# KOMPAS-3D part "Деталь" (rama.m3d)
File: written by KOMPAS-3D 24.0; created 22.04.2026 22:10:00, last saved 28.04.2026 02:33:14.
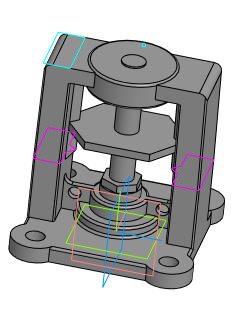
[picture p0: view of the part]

Document properties: Автор: mrdid; Полное имя файла: C:\Работа\ГОТОВЫЕ ИСХОДНИКИ\VSO2130M-F-S Клапан запорный сильфонный DN.ru Ду15-100 Ру40\исходные материалы\DN50\rama.m3d

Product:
- Part/product: Деталь
    Масса: 2.809972

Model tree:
1. Эскиз:2  (with: Ребро.Элемент выдавливания:14)
2. Элемент выдавливания:1
     Расстояние 1 = 10
3. Эскиз:3  (with: Грань.Элемент выдавливания:1, Ребро.Элемент выдавливания:1)
4. Элемент выдавливания:2
     Расстояние 2 = 10
5. Массив по сетке:1  (with: Элемент выдавливания:2, Эскиз:3)  (4 pattern instances)
     Угол раствора = 90
6. Эскиз:4  (with: Грань.Элемент выдавливания:1)
7. Элемент выдавливания:3
     Расстояние 1 = 7
8. Эскиз:5  (with: Грань.Элемент выдавливания:3, Ребро.Элемент выдавливания:3)
9. Элемент выдавливания:4
     Расстояние 1 = 10
10. Эскиз:6  (with: Грань.Элемент выдавливания:1, Ребро.Элемент выдавливания:1)
11. Элемент выдавливания:5
     Расстояние 1 = 40
12. Эскиз:23  (with: Грань.Элемент выдавливания:4, Ребро.Элемент выдавливания:4)
13. Элемент выдавливания:21
     Расстояние 1 = 11
14. Эскиз:7  (with: Грань.Элемент выдавливания:21, Ребро.Элемент выдавливания:3)
15. Элемент выдавливания:6
     Расстояние 2 = 5
16. Эскиз:8  (with: Грань.Элемент выдавливания:5, Ребро.Элемент выдавливания:5)
17. Смещенная плоскость:1  (with: Грань.Элемент выдавливания:5)
18. Эскиз:9
19. Элемент по сечениям:1
20. Элемент по сечениям:2
21. Эскиз:10
22. Элемент выдавливания:8
     Расстояние 2 = 10
23. Эскиз:11  (with: Грань.Элемент выдавливания:8, Ребро.Элемент выдавливания:3)
24. Элемент выдавливания:9  (with: Грань.Элемент выдавливания:8)
     Расстояние 1 = 1; Расстояние 2 = 16; Смещение 2 = 6
25. Эскиз:12  (with: Грань.Элемент выдавливания:9, Ребро.Элемент выдавливания:9)
26. Элемент выдавливания:10
     Расстояние 1 = 5
27. Эскиз:13  (with: Грань.Элемент выдавливания:21, Ребро.Элемент выдавливания:3)
28. Элемент выдавливания:11  (with: Грань.Элемент выдавливания:10)
     Расстояние 1 = 56.64
29. Смещенная плоскость:2  (with: Грань.Элемент выдавливания:21)
30. Эскиз:14  (with: Ребро.Элемент по сечениям:2, Ребро.Элемент по сечениям:1)
31. Элемент выдавливания:12
     Расстояние 1 = 5
32. Эскиз:15  (with: Грань.Элемент выдавливания:12, Ребро.Элемент выдавливания:3)
33. Элемент выдавливания:13
     Расстояние 1 = 5
34. Эскиз:16  (with: Ребро.Элемент выдавливания:5, Ребро.Элемент выдавливания:1, Ребро.Элемент выдавливания:4)
35. Элемент выдавливания:14
     Расстояние 1 = 4
36. Элемент выдавливания:15
     Расстояние 1 = 2
37. Эскиз:17  (with: Ребро.Элемент выдавливания:14, Ребро.Элемент выдавливания:5)
38. Элемент выдавливания:16
     Расстояние 1 = 56; Расстояние 2 = 56
39. Скругление:1  (with: Ребро.Элемент выдавливания:1, Ребро.Элемент выдавливания:3)
     Радиус = 1.5
40. Скругление:2  (with: Ребро.Элемент выдавливания:9, Ребро.Элемент выдавливания:10, Ребро.Элемент выдавливания:13, Ребро.Элемент выдавливания:4)
41. Эскиз:18  (with: Грань.Элемент выдавливания:9)
42. Элемент выдавливания:17
     Расстояние 1 = 1
43. Скругление:3  (with: Ребро.Элемент по сечениям:2, Ребро.Элемент по сечениям:1)
     Радиус = 5
44. Скругление:4  (with: Ребро.Элемент выдавливания:8)
     Радиус = 0.5
45. Скругление:5  (with: Ребро.Элемент выдавливания:14)
     Радиус = 5
46. Эскиз:19  (with: Ребро.Элемент выдавливания:17)
47. Элемент выдавливания:18  (with: Грань.Элемент выдавливания:9)
     Смещение 1 = 5
48. Смещенная плоскость:3  (with: Грань.Элемент выдавливания:18)
     Расстояние = 2
49. Эскиз:20  (with: Ребро.Элемент выдавливания:18)
50. Элемент выдавливания:19
     Расстояние 2 = 0.2
51. Скругление:6  (with: Ребро.Элемент выдавливания:18)
     Радиус = 1
52. Эскиз:21  (with: Ребро.Элемент выдавливания:19)
53. Элемент выдавливания:20
     Расстояние 1 = 10
54. Скругление:7  (with: Ребро.Элемент по сечениям:2, Ребро.Элемент выдавливания:5, Ребро.Элемент по сечениям:1)
     Радиус = 1
55. Фаска:1  (with: Ребро.Элемент по сечениям:1, Ребро.Элемент по сечениям:2)
     Угол = 45; Длина 1 = 5; Длина 2 = 5
56. Массив по концентрической сетке:1  (with: Элемент выдавливания:2, Эскиз:3)  (labels: Клапан запорный DN.ru Ду50 Ру40)  (4 pattern instances)
     Шаг 2 = 360

Expressions: v249/2; D2-3*2; DN/2; DN/3
Referenced files in C:\Работа\ГОТОВЫЕ ИСХОДНИКИ\VSO2130M-F-S Клапан запорный сильфонный DN.ru Ду15-100 Ру40\исходные материалы\DN50\: VSO2130M-F-S Клапан запорный DN.ru Ду50 Ру40.a3d
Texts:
  DN+5
  DN-10
  Ось Y.Начало координат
